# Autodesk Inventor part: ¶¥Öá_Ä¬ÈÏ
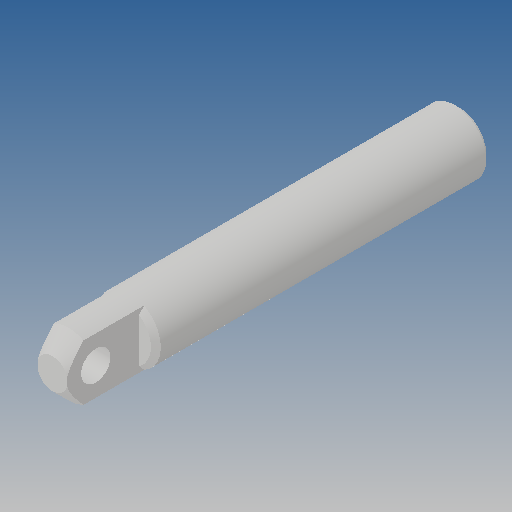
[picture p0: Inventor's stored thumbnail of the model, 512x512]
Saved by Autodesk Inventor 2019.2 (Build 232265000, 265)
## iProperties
Created: 2012-09
Part Number: ¶¥Öá_Ä¬ÈÏ
Material: Ogólny
Document SubType Name: Modeling
Designer: CADENGINEERING4
Density: 1 g/cm^3
Appearance: Domyślna
Author: CADENGINEERING4
Revision Number: ÈÎºÎ
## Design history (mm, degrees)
feature "NONE"
node "Bryła1"
